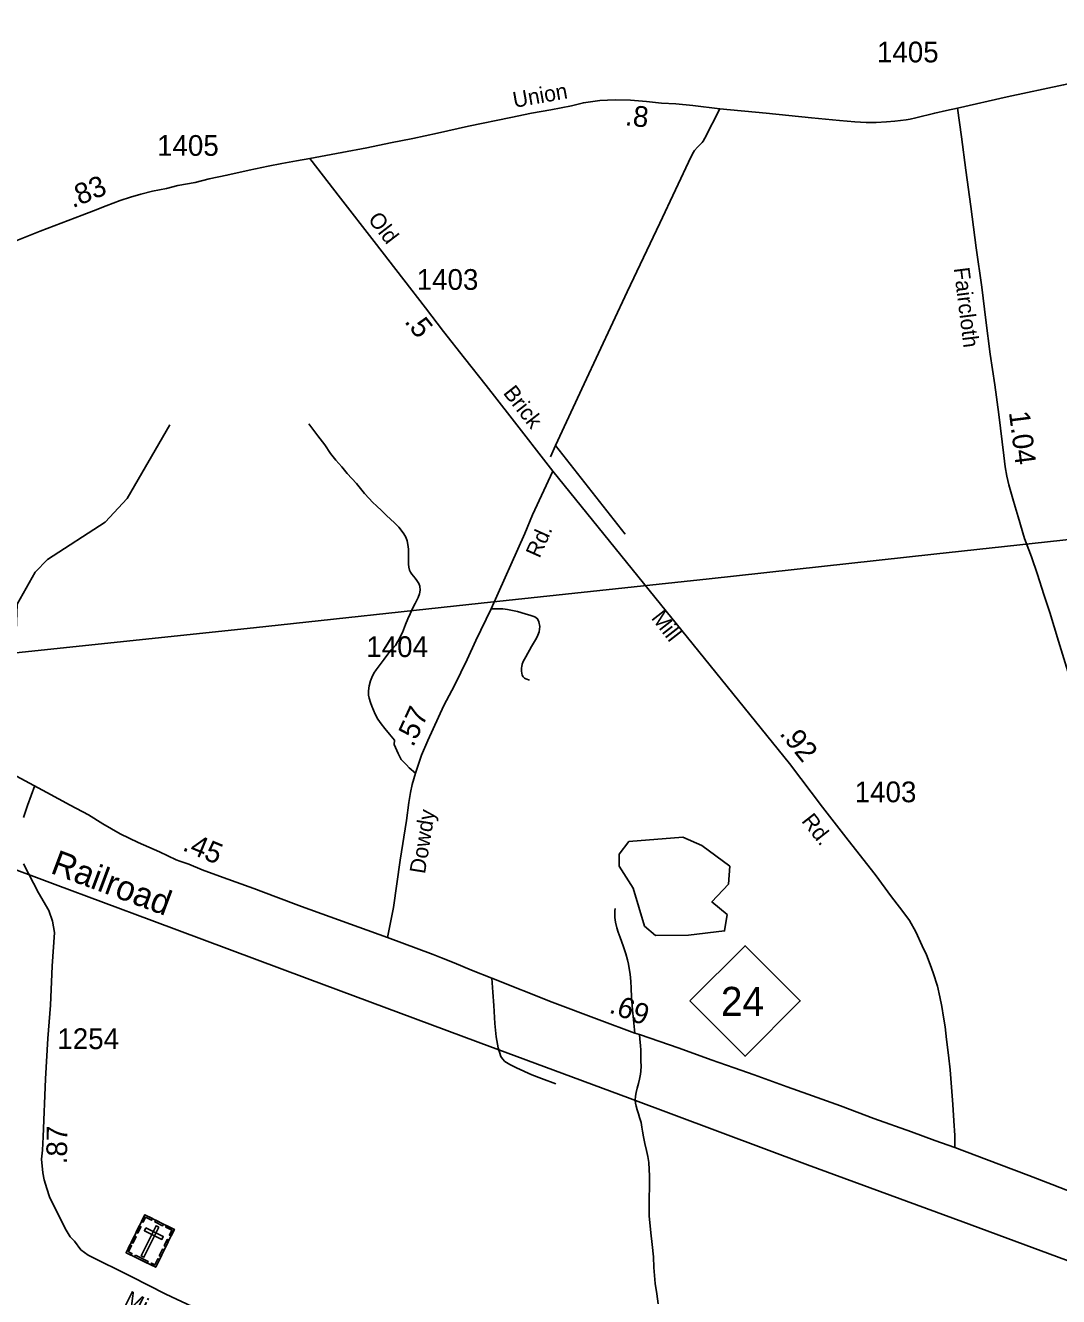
# Model space of a CAD drawing. Extents: x 2093524 to 2270757, y 289120 to 570408.
# Drawn here: x 2134238 to 2140469, y 441355 to 449022 of the extents above; entities that cross this region are included whole.
import ezdxf

# ---------------------------------------------------------------- set-up
doc = ezdxf.new("R2010")
doc.units = 0
for name, color, linetype in [('Exist Cultural Cemetery CELL', 7, 'Continuous'), ('Exist Hydrographic Creek Single Shore', 7, 'Continuous'), ('Exist Hydrographic Pond Under 1500 Sq Ft', 7, 'Continuous'), ('Exist Railroad Mainline', 7, 'Continuous'), ('Exist Railroad Mainline Label', 7, 'Continuous'), ('Exist Road Non-System Type 51', 7, 'Continuous'), ('Exist Road Primary NC Attributed', 7, 'Continuous'), ('Exist Road Primary NC Mileage Hundredths English Label', 7, 'Continuous'), ('Exist Road Primary NC Shield CELL', 7, 'Continuous'), ('Exist Road Primary NC Shield Number Label', 7, 'Continuous'), ('Exist Road Secondary Mileage Hundredths English Label', 7, 'Continuous'), ('Exist Road Secondary Type 51 Attributed', 7, 'Continuous'), ('Exist Road Secondary Type 51 Label', 7, 'Continuous'), ('Exist Road Secondary Type 51 Number Label', 7, 'Continuous'), ('Exist Utilities Telephone Line', 7, 'Continuous')]:
    doc.layers.add(name, color=color, linetype=linetype)

msp = doc.modelspace()

# ---------------------------------------------------------------- linework, layer by layer
at = {"layer": 'Exist Cultural Cemetery CELL'}
for points in [[(2134957.1, 441848.1), (2135135.7, 441760.1), (2135023.3, 441531.7), (2134844.7, 441619.6)], [(2134938, 441809.2), (2134948.2, 441804.2), (2134962.4, 441833.1), (2134998.8, 441815.2), (2135003.7, 441825.1), (2134957.1, 441848.1)], [(2134905.2, 441742.7), (2134924.4, 441781.6), (2134934.6, 441776.5), (2134915.4, 441737.7)], [(2135042, 441773.6), (2135025.2, 441781.9), (2134935.7, 441599.9), (2134952.4, 441591.7)], [(2134963.7, 441769), (2134955.4, 441752.2), (2135061.1, 441700.2), (2135069.3, 441717)], [(2135023.6, 441815.3), (2135070.1, 441792.4), (2135065, 441782.2), (2135018.5, 441805.1)], [(2135116.7, 441721.2), (2135106.5, 441726.2), (2135120.7, 441755.1), (2135084.3, 441773), (2135089.2, 441783), (2135135.8, 441760.1)], [(2134875.5, 441682.4), (2134894.7, 441721.3), (2134904.9, 441716.2), (2134885.7, 441677.4)], [(2135074.1, 441660.7), (2135093.3, 441699.5), (2135103.5, 441694.5), (2135084.4, 441655.6)], [(2134874.4, 441605.1), (2134879.4, 441615.4), (2134859.7, 441625.1), (2134877.5, 441661.3), (2134867.6, 441666.3), (2134844.6, 441619.7)], [(2135045, 441601.5), (2135064.1, 441640.4), (2135074.3, 441635.4), (2135055.2, 441596.5)], [(2134901.3, 441604.5), (2134977.4, 441567.1), (2134972.4, 441556.8), (2134896.2, 441594.3)], [(2134993.5, 441546.3), (2134998.6, 441556.6), (2135018.4, 441546.9), (2135036.2, 441583.2), (2135046.2, 441578.3), (2135023.3, 441531.7)]]:
    msp.add_lwpolyline(points, close=True, dxfattribs=at)
at = {"layer": 'Exist Hydrographic Creek Single Shore'}
msp.add_lwpolyline([(2133656.1, 441665), (2133705.1, 441880.6), (2133711.1, 442349.5), (2133750, 442880.2), (2133757, 443306.6), (2133663.1, 443715.2), (2133663.1, 443839.8), (2133836, 444197.3), (2133910, 444497.6), (2134100.1, 444782.4), (2134166.1, 444941.8), (2134188, 445531.9), (2134296.1, 445723.3), (2134370.1, 445800.5), (2134719.1, 446026.5), (2134852, 446168.2), (2135108.1, 446612.4)], dxfattribs=at)
at = {"layer": 'Exist Hydrographic Pond Under 1500 Sq Ft'}
msp.add_lwpolyline([(2138237.2, 443535.2), (2138454.1, 443560.5), (2138470.1, 443658.5), (2138378.3, 443735.8), (2138478.1, 443842.1), (2138486.1, 443950.2), (2138318.2, 444074.9), (2138202.1, 444126.5), (2137877.1, 444100.1), (2137819.1, 444022.5), (2137819.1, 443950.4), (2137903.2, 443817.5), (2137971.2, 443589.7), (2138038.1, 443532.7), (2138237.2, 443535.2)], dxfattribs=at)
at = {"layer": 'Exist Railroad Mainline'}
for points in [[(2131210.9, 445029.9), (2132048.1, 444722), (2132927.1, 444396.3), (2134416.4, 443840.6)], [(2134416.4, 443840.6), (2134999.7, 443622.7), (2135936.8, 443273.2), (2136968.1, 442890.3), (2137885.2, 442548.8), (2138954.5, 442150.1), (2139891.7, 441804.9), (2140836.9, 441455.4), (2141728, 441127.9), (2142288.6, 440918.7), (2142709.3, 440762.8), (2142977.5, 440666)]]:
    msp.add_lwpolyline(points, dxfattribs=at)
at = {"layer": 'Exist Road Non-System Type 51'}
for p, q in [((2137404.7, 446419.2), (2137434.7, 446487.2)), ((2137434.7, 446487.2), (2137855.3, 445952.5))]:
    msp.add_line(p, q, dxfattribs=at)
for points in [[(2137434.7, 446487.2), (2137607.5, 446860.5), (2137866.6, 447415.7), (2138063.4, 447829.1), (2138252.2, 448230.5), (2138266.1, 448256.4), (2138272.1, 448266.5), (2138292.1, 448288.3), (2138318.3, 448316.4), (2138326.3, 448324.2), (2138334.4, 448342.2), (2138426.6, 448519.2)], [(2136590.4, 444512.2), (2136552.9, 444544), (2136535.8, 444562.1), (2136503.8, 444595.1), (2136485.9, 444631.1), (2136461.8, 444685.3), (2136463.5, 444710.2), (2136433.4, 444746.2), (2136405.5, 444780.3), (2136383.7, 444810.3), (2136363.6, 444838.3), (2136347.8, 444868.4), (2136326, 444916.5), (2136318, 444938.4), (2136310, 444964.4), (2136306.5, 444981.7), (2136306, 445008.5), (2136310.2, 445038.4), (2136318.2, 445068.4), (2136326.2, 445088.3), (2136338.3, 445114.2), (2136352.3, 445134.3), (2136370.5, 445160.2), (2136400.5, 445200.2), (2136422.5, 445230.1), (2136442.5, 445253.9), (2136451.5, 445262.3), (2136468.7, 445282), (2136482.7, 445303.9), (2136490, 445316.8), (2136500.8, 445337.7), (2136511, 445360.5), (2136530.8, 445407.7), (2136544.9, 445441.7), (2136558.9, 445473.6), (2136571.1, 445501.5), (2136589.1, 445535.6), (2136607.3, 445571.4), (2136615.3, 445593.4), (2136619.3, 445615.3), (2136617.4, 445639.4), (2136611.1, 445656.3), (2136599.1, 445673.9), (2136587.4, 445687.4), (2136577.4, 445699.6), (2136567.5, 445711.6), (2136559.5, 445723.5), (2136553.5, 445735.4), (2136549.7, 445753.5), (2136548.7, 445772.7), (2136547.7, 445803.6), (2136547.9, 445831.6), (2136547.9, 445863.5), (2136543.8, 445891.4), (2136539.9, 445913.5), (2136532.1, 445935.9), (2136520.1, 445955.5), (2136509, 445970.1), (2136490.1, 445995.5), (2136464.3, 446021.6), (2136416.3, 446065.7), (2136384.5, 446095.8), (2136356.5, 446121.7), (2136330.5, 446145.9), (2136310.6, 446167.8), (2136282.8, 446198), (2136234.8, 446258), (2136179, 446320.1), (2136145.2, 446360.1), (2136109.2, 446400.2), (2136077.5, 446440.3), (2136043.5, 446492.3), (2136001.6, 446546.4), (2135947.8, 446618.6)], [(2137277.9, 445073.3), (2137256, 445081.4), (2137247.9, 445085.3), (2137240.1, 445093.5), (2137234.1, 445103.4), (2137230.3, 445126.7), (2137230.2, 445147.5), (2137231.9, 445154.9), (2137234.2, 445169.4), (2137240.1, 445185.5), (2137256.3, 445213.4), (2137290.3, 445275.3), (2137308.5, 445305.1), (2137320.5, 445325.1), (2137328.5, 445345.1), (2137336.5, 445365.1), (2137340.5, 445397.1), (2137334.7, 445425), (2137326.7, 445443.1), (2137310.7, 445455), (2137286.6, 445462.3), (2137250.9, 445473.2), (2137205, 445487.4), (2137145, 445499.5), (2137116.9, 445503.5), (2137046.2, 445503.9)], [(2137912.7, 442943.6), (2137899, 443083.5), (2137892.8, 443161.2), (2137891.3, 443215.4), (2137889.3, 443254.9), (2137884.3, 443298.6), (2137879.6, 443333.4), (2137875, 443359.9), (2137869.7, 443385.4), (2137859.8, 443421.4), (2137842, 443471.4), (2137824, 443521.5), (2137812, 443553.6), (2137804.2, 443579.5), (2137796.2, 443613.5), (2137792.4, 443641.6), (2137792.4, 443663.6), (2137792.4, 443681.5), (2137794.5, 443695.5)], [(2137436.4, 442638.8), (2137350.5, 442671.1), (2137292.5, 442693), (2137198.8, 442735.3), (2137158.8, 442755.3), (2137128.7, 442773.5), (2137114.9, 442789.6), (2137104.9, 442803.6), (2137089.2, 442854.5), (2137075.9, 442921.7), (2137069.3, 443001.4), (2137063.6, 443109.6), (2137057.7, 443191.5), (2137050, 443275.4)], [(2138053.1, 441312), (2138045.3, 441372), (2138035.1, 441433.1), (2138027.6, 441529.9), (2138025.7, 441593.9), (2138017.8, 441669.9), (2138010, 441739.8), (2138004.2, 441801.7), (2138000.2, 441839.8), (2138000.3, 441873.8), (2138000.6, 441947.8), (2138000.8, 442017.8), (2138000.9, 442083.8), (2138000.2, 442121.4), (2137997.1, 442163.6), (2137991, 442199.7), (2137983.1, 442235.7), (2137973.3, 442277.3), (2137965.5, 442317.6), (2137959.4, 442351.8), (2137955.5, 442377.6), (2137950.7, 442404.9), (2137941.7, 442435.7), (2137934.3, 442456.4), (2137927.6, 442480.4), (2137920.9, 442502.9), (2137917.8, 442521.8), (2137915.6, 442539.2), (2137917.9, 442563.8), (2137921.9, 442585.7), (2137928, 442611.6), (2137936, 442639.6), (2137942.1, 442665.7), (2137948.1, 442695.5), (2137950.3, 442715.5), (2137950.9, 442745.1), (2137950.3, 442775.5), (2137950.3, 442807.5), (2137948.6, 442839.5), (2137946.6, 442871.6), (2137945.1, 442886.2), (2137940.7, 442935.5)]]:
    msp.add_lwpolyline(points, dxfattribs=at)
at = {"layer": 'Exist Road Primary NC Attributed'}
for points in [[(2131685, 445865.6), (2131857, 445771.8), (2132067.1, 445656.6), (2132229.5, 445570.9), (2132354.8, 445499.1), (2132441.2, 445455.7), (2132537.6, 445402.7), (2132616.4, 445357.5), (2132740.2, 445287.3), (2132827, 445235.8), (2132989.1, 445150.6), (2133094.5, 445089.7), (2133261.9, 444996), (2133485.1, 444871.4), (2133648.8, 444779.6), (2133841.7, 444673.6), (2134054.8, 444561.7), (2134262.5, 444450.9)], [(2134262.5, 444450.9), (2134366.8, 444395.4), (2134507, 444318.2), (2134617.3, 444260.6), (2134705.1, 444206.8), (2134809.6, 444145.9), (2134917.3, 444094.5), (2135045.9, 444036.8), (2135147.2, 443990), (2135169.3, 443980.9), (2135224, 443962.2), (2135302.7, 443929.5), (2135429.7, 443882.7), (2135615.8, 443815.8), (2135747.6, 443765.9), (2135902, 443708.2), (2136421.8, 443520.1)], [(2136421.8, 443520.1), (2136696.4, 443418.2), (2136746.4, 443398), (2136824.2, 443367.9), (2136928.1, 443323.6), (2137050, 443275.4), (2137415.4, 443130.5), (2137697.1, 443023.9), (2137912.7, 442943.6), (2137940.7, 442935.5), (2138180.4, 442852.9), (2138374.2, 442782.4), (2138512, 442734.3), (2138632.6, 442691.7), (2138743.7, 442651.7), (2138831.5, 442619.5), (2138957.4, 442575.2), (2139153.2, 442504.7), (2139354.8, 442428.3), (2139582.6, 442348), (2139722.3, 442295.6), (2139842.3, 442253.4)], [(2139842.3, 442253.4), (2140107.9, 442152.7), (2140289.7, 442084.3), (2140429.4, 442030.1), (2140559.2, 441979.7), (2140667.1, 441937.6), (2140816.8, 441881.2), (2140962.6, 441824.9), (2141110.5, 441769.8), (2141284.2, 441704.1), (2141474, 441633.7), (2141635.7, 441573.5), (2141762.4, 441527), (2141811.4, 441509), (2141985.3, 441444.7)]]:
    msp.add_lwpolyline(points, dxfattribs=at)
at = {"layer": 'Exist Road Primary NC Shield CELL'}
msp.add_lwpolyline([(2138245, 443137.7), (2138578, 443470.7), (2138911, 443137.7), (2138578, 442804.7)], close=True, dxfattribs=at)
at = {"layer": 'Exist Road Secondary Type 51 Attributed'}
for points in [[(2139859.4, 448522.7), (2140158.4, 448591), (2140499.2, 448662.5), (2140815.9, 448731.8), (2141090.2, 448790.2), (2141330.5, 448840.2), (2141670.8, 448913.8), (2141946.3, 448974.1), (2142115.1, 449021.7)], [(2135953.8, 448219.6), (2136146.4, 448255.2), (2136296.6, 448283.7), (2136439.4, 448313.3), (2136573.2, 448340.6), (2136723.4, 448372.5), (2136910.9, 448413.4), (2137164.3, 448465.7), (2137290.8, 448492.9), (2137405.8, 448513.4), (2137531.1, 448537.3), (2137602.7, 448555.5), (2137702.4, 448568), (2137794.8, 448572.5), (2137886.3, 448571.4), (2137983.7, 448562.3), (2138074.1, 448553.2), (2138159.8, 448548.6), (2138263.8, 448538.4), (2138426.6, 448519.2), (2138704.7, 448493), (2138979.1, 448464.6), (2139146.6, 448448.6), (2139240.5, 448440.7), (2139308.5, 448437.2), (2139368.4, 448437.2), (2139431.7, 448439.5), (2139480.6, 448445.1), (2139548.7, 448453.1), (2139574.5, 448457.2), (2139608.5, 448465.1), (2139722.4, 448492.6), (2139792.5, 448508.4), (2139859.4, 448522.7)], [(2140532, 445098.5), (2140468.4, 445308.6), (2140416.9, 445480.6), (2140379.2, 445588.5), (2140341.5, 445710.7), (2140305.8, 445816.8), (2140264, 445926.8), (2140224.2, 446058.8), (2140207, 446117.3), (2140192.8, 446166.4), (2140180.2, 446208.6), (2140168.7, 446250.9), (2140156.9, 446302.9), (2140147, 446358.9), (2140139.2, 446428.8), (2140107.8, 446674.8), (2140084.1, 446854.7), (2140056.6, 447038.8), (2140030.9, 447244.7), (2140005.5, 447442.6), (2139972.1, 447680.6), (2139940.6, 447928.6), (2139909, 448148.6), (2139883.4, 448350.5), (2139859.4, 448522.7)], [(2134105.3, 447691.8), (2134325.8, 447781.2), (2134578.9, 447878), (2134648.4, 447903), (2134724.6, 447934.4), (2134809.1, 447966.6), (2134870.9, 447986.9), (2134933.8, 448004.4), (2135004.1, 448021.1), (2135087.5, 448039.1), (2135157.4, 448055.3), (2135261.2, 448074.7), (2135345.6, 448095.9), (2135453.2, 448118), (2135586.2, 448148.4), (2135702.4, 448172.4), (2135784.3, 448188.2), (2135872.9, 448204.8), (2135953.8, 448219.6)], [(2135953.8, 448219.6), (2136138.9, 447979.8), (2136340.6, 447717.6), (2136519.6, 447486.6), (2136650.7, 447319.2), (2136759.2, 447176), (2136886.5, 447015.6), (2137016.9, 446849.6), (2137158.6, 446668), (2137419.4, 446333)], [(2137419.4, 446333), (2137296.7, 446070.6), (2137249, 445958), (2137046.2, 445503.9), (2136955, 445312.9), (2136902, 445197.5), (2136826.4, 445041.5), (2136761.6, 444919.4), (2136665.2, 444709.7), (2136625.8, 444619.8), (2136590.4, 444512.2), (2136569.6, 444444.1), (2136560, 444395.7), (2136550.3, 444334.9), (2136535.8, 444227.3), (2136497.4, 443986.3), (2136457.2, 443702.5), (2136421.8, 443520.1)], [(2137419.4, 446333), (2138845.9, 444570.6), (2139045.2, 444306.3), (2139200.6, 444108), (2139362, 443899.8), (2139461.7, 443765.6), (2139509.5, 443703.5), (2139547.5, 443653.3), (2139569.3, 443623.3), (2139607.1, 443555.4), (2139647, 443471.2), (2139672.9, 443415.3), (2139694.7, 443357.2), (2139712.5, 443307.1), (2139738.3, 443227.2), (2139752.3, 443163.1), (2139764.1, 443105.1), (2139774, 443041.1), (2139785.8, 442981.1), (2139793.7, 442905.1), (2139805.4, 442811.1), (2139815.3, 442723.1), (2139821.1, 442643.2), (2139830.7, 442513.2), (2139836.5, 442415.3), (2139842.4, 442327.2), (2139842.3, 442253.4)], [(2134226.1, 444244.4), (2134251.1, 444316.6), (2134294.7, 444436.9)], [(2135243.6, 441294.9), (2135085.3, 441370.2), (2134875, 441475.2), (2134615.1, 441604.8), (2134570.9, 441637.2), (2134534.1, 441689), (2134507.8, 441715.3), (2134478.1, 441765.4), (2134383.7, 441957.1), (2134366.6, 442007.2), (2134351.3, 442059.5), (2134342.5, 442102.2), (2134335.1, 442183.3), (2134341, 442237.1), (2134345.4, 442318.1), (2134358.7, 442667.4), (2134372.2, 442912.1), (2134389.2, 443112.1), (2134397.9, 443348.1), (2134413.2, 443551), (2134401.4, 443620.2), (2134377.9, 443683.6), (2134316, 443789.7), (2134226.1, 443965.1)]]:
    msp.add_lwpolyline(points, dxfattribs=at)
at = {"layer": 'Exist Utilities Telephone Line'}
msp.add_lwpolyline([(2132406.6, 445046.7), (2134256.6, 445245.3), (2135613.1, 445387.6), (2136985.5, 445538), (2138361.9, 445684.6), (2139716.4, 445832.9), (2141086.8, 445981.6), (2142443.5, 446129.9), (2143887.7, 446290.7), (2144792.7, 446393), (2145242.2, 446441), (2145651.3, 446549)], dxfattribs=at)

# ---------------------------------------------------------------- texts
at = {"layer": 'Exist Railroad Mainline Label'}
msp.add_text('Railroad', height=150, rotation=339.514, dxfattribs=at).set_placement((2134382.3, 443911.4))
at = {"layer": 'Exist Road Primary NC Mileage Hundredths English Label'}
for s, rotation, p in [('.45', 337.42535, (2135178.8, 444048.7)), ('.69', 339.57258, (2137752.7, 443069.9))]:
    msp.add_text(s, height=125, rotation=rotation, dxfattribs=at).set_placement(p)
at = {"layer": 'Exist Road Primary NC Shield Number Label'}
msp.add_text('24', height=175, dxfattribs=at).set_placement((2138432.2, 443048))
at = {"layer": 'Exist Road Secondary Mileage Hundredths English Label'}
for s, rotation, p in [('.8', 353.90519, (2137850.8, 448420.2)), ('.83', 22.40945, (2134522.7, 447918.7)), ('.5', 308.49285, (2136519.5, 447234.6)), ('1.04', 277.27432, (2140169, 446688.8)), ('.57', 65.3119, (2136575.7, 444664.7)), ('.92', 308.9878, (2138781.8, 444749.1)), ('.87', 89.47279, (2134488.4, 442152.4))]:
    msp.add_text(s, height=125, rotation=rotation, dxfattribs=at).set_placement(p)
at = {"layer": 'Exist Road Secondary Type 51 Label'}
for s, rotation, p in [('Union', 10.1046, (2137186.1, 448524.2)), ('Old', 307.57345, (2136299.7, 447851.4)), ('Faircloth', 277.11445, (2139836.3, 447557.5)), ('Brick', 307.89873, (2137115, 446804.2)), ('Rd.', 65.94534, (2137338, 445804)), ('Mill', 307.90628, (2138008, 445446.7)), ('Dowdy', 80.92801, (2136647.4, 443901)), ('Rd.', 308.08439, (2138914.3, 444222.4)), ('Microwave', 333.46749, (2134827.5, 441308.8))]:
    msp.add_text(s, height=95, rotation=rotation, dxfattribs=at).set_placement(p)
at = {"layer": 'Exist Road Secondary Type 51 Number Label'}
for s, p in [('1405', (2139373.7, 448798.8)), ('1405', (2135031.8, 448235.2)), ('1403', (2136597.7, 447427)), ('1404', (2136293.8, 445212.3)), ('1403', (2139239.4, 444336.4)), ('1254', (2134430.3, 442847.7))]:
    msp.add_text(s, height=125, dxfattribs=at).set_placement(p)

doc.saveas('drawing.dxf')
